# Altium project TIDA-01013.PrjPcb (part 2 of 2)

## Sheet TIDA-01013_EVM_Hardware.SchDoc
size 431 x 279 mm; Date: Not shown in title block; ApprovedBy: Not shown in title block; CheckedBy: Not shown in title block; Author: Not shown in title block; CompanyName: Not shown in title block; Engineer: Not shown in title block; Organization: Not shown in title block; Address1: Not shown in title block; Address2: Not shown in title block; Address3: Not shown in title block; Address4: Not shown in title block; DocumentNumber: 1; Revision: Use project parameter SCH_Rev; SheetNumber: 6; SheetTotal: 6; PageSetup: Record=PageOptions¦CenterHorizontal=True¦CenterVertical=True¦PrintScale=1.00¦XCorrection=1.00¦YCorrection=1.00¦PrintKind=0¦BorderSize=5000000¦LeftOffset=0¦BottomOffset=0¦Orientation=2¦PaperLength=1000¦PaperWidth=1000¦Scale=100¦PaperSource=15¦PrintQuality=600¦MediaType=1¦DitherType=10¦PaperKind=Letter¦PrintScaleMode=1
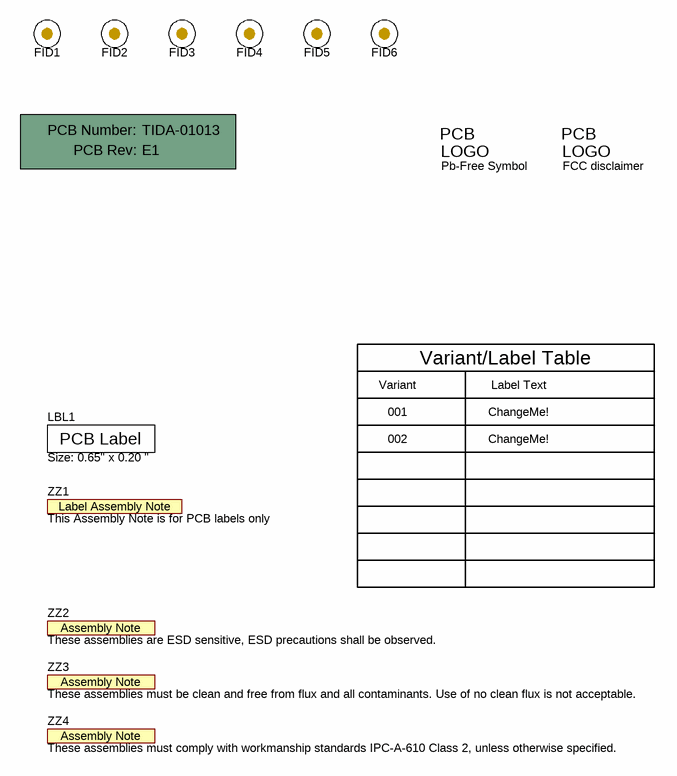
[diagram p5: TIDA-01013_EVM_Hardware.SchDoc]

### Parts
!PCB  Printed Circuit Board  (value not drawn)  (mechanical)
FID1  Fiducial  [Fiducial10-20]  (value not drawn)
FID2  Fiducial  [Fiducial10-20]  (value not drawn)
FID3  Fiducial  [Fiducial10-20]  (value not drawn)
FID4  Fiducial  [Fiducial10-20]  (value not drawn)
FID5  Fiducial  [Fiducial10-20]  (value not drawn)
FID6  Fiducial  [Fiducial10-20]  (value not drawn)
LBL1  Size: 0.65" x 0.20 "  [Label_650x200]
Logo2  Pb-Free Symbol  [Pb-Free_Overlay_Small]  (no BOM)
Logo3  FCC disclaimer  [FCC_disclaimer]  (no BOM)
ZZ1  This Assembly Note is for PCB labels only  [AssemblyNoteLabel]  (no BOM)
ZZ2  These assemblies are ESD sensitive, ESD precautions shall be observed.  [AssemblyNote]  (no BOM)
ZZ3  These assemblies must be clean and free from flux and all contaminants. Use of no clean flux is not acceptable.  [AssemblyNote]  (no BOM)
ZZ4  These assemblies must comply with workmanship standards IPC-A-610 Class 2, unless otherwise specified.  [AssemblyNote]  (no BOM)

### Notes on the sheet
- Variant
- Variant/Label Table
- Label Text
- 001
- 002
- ChangeMe!

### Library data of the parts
!PCB = PCB: Manufacturer: Any; PartNumber: TIDA-01013; SymbolCreator: a0412235
FID1-FID6 = Fiducial: Fiducial mark.  There is nothing to buy or mount.; SymbolCreator: codlsc
LBL1 = THT-14-423-10: Thermal Transfer Printable Labels, 0.650" W x 0.200" H - 10,000 per roll; Manufacturer: Brady; SymbolCreator: a0412235; CompType: Label
Logo2 = Pb-Free: SymbolCreator: a0412235
Logo3 = FCC_disclaimer: SymbolCreator: codlsc
ZZ1 = AssemblyNoteLabel: SymbolCreator: a0412235
ZZ2-ZZ4 = AssemblyNote: SymbolCreator: codlsc

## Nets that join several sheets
3.3V: LP_Front_End_PWR (J1.2), LP_Front_End_AFE (C46.1 U10.1 U10.2)
5.2V: LP_Front_End_PWR (J5.2), LP_Front_End_AFE (C56.2 C86.2 U12.5 U18.5)
-5.2V: LP_Front_End_PWR (J4.2), LP_Front_End_AFE (C61.2 C87.2 U12.2 U18.2)
ADC_3.3V: LP_Front_End_PWR (J12.2), LP_Front_End_ADC (6 pins)
AGND: LP_Front_End_PWR (65 pins), LP_Front_End_AFE (26 pins), LP_Front_End_ADC (20 pins)
D1.8V: LP_Front_End_PWR (J3.2), LP_Front_End_ClockTree (8 pins), LP_Front_End_ADC (11 pins)
D3.3V: LP_Front_End_PWR (J2.2), LP_Front_End_ClockTree (6 pins)
DGND: LP_Front_End_ClockTree (16 pins), LP_Front_End_ADC (27 pins)
THS_3.3V: LP_Front_End_PWR (J11.2), LP_Front_End_AFE (7 pins)
3V_REF: LP_Front_End_AFE (C47.1 U10.5 U10.6), LP_Front_End_ADC (C75.1 C76.2 U14.9)
ADS127L01_DIGITAL_CLK: LP_Front_End_ClockTree (R68.1 R69.1 R70.1), LP_Front_End_ADC (R47.2)
AINN: LP_Front_End_AFE (C55.1 R38.2), LP_Front_End_ADC (U14.3)
AINP: LP_Front_End_AFE (C55.2 R43.2), LP_Front_End_ADC (U14.4)

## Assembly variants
001: not fitted C5 C20 C33 R4 R10 R12 R17 R26 R42 R50 R53 R55 R59 R61 R63 R68 R69 R71 R78 R79 R80 R81 R82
